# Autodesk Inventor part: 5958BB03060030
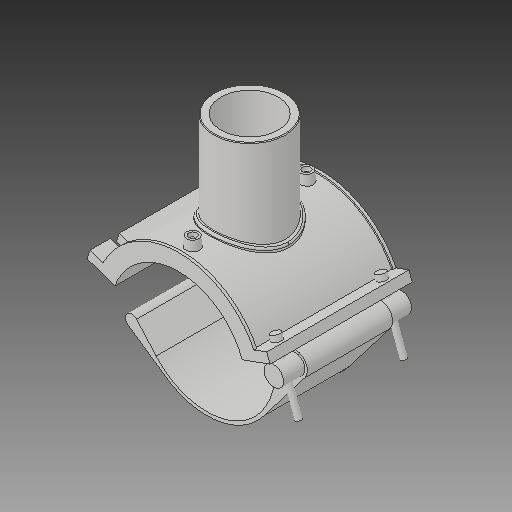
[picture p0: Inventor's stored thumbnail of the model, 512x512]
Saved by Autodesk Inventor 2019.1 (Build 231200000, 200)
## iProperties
Created: 2017-07
Part Number: 5958BB03060030
Material: Generic
Description: PLASSON BRANCH SADDLE 6'' x 3''
Document SubType Name: Modeling
Designer: KIM
Mass: 764.267 g
Surface Area: 1930.38 cm^2
Volume: 764.267 cm^3
Density: 1 g/cm^3
Appearance: Default
Author: KIM
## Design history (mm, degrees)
derived "5958B.ipt"
feature "Solid1::5958B.ipt"
feature "Solid2::5958B.ipt"
feature "Solid3::5958B.ipt"
tag "TaggingFeature1"
body "Solid1"
body "Solid2"
body "Solid3"
other parameters: "d_" = 168, "B_" = 173.736, "H_" = 106.934, "L_" = 176.022, "d_t" = 6, "d_1" = 88.7, "H_1" = 88.646, "d1" = 204.576, "d148" = 4.2, "d160" = 4.2, "d0" = 168, "d2" = 225.8568, "d3" = 42, "d4" = 176.022, "d5" = 0, "d6" = 0.1, "d8" = 0, "d19" = 6, "d20" = 6, "d21" = 105.6132, "d23" = 0, "d24" = 52.8066, "d26" = 0, "d27" = 3, "d28" = 3, "d29" = 3, "d30" = 56, "d31" = 6, "d32" = 0, "d33" = 0, "d34" = 0.6, "d40" = 106.37952, "d41" = 97.57, "d43" = 0, "d45" = 0, "d47" = 209.222, "d48" = 88.7, "d50" = 0, "d70" = 15, "d72" = 0, "d73" = 6, "d75" = 5, "d76" = 0, "d77" = 8.4, "d78" = 114, "d79" = 15, "d80" = 70.4088, "d82" = 5 deg, "d84" = 4, "d85" = 14, "d86" = 0, "d87" = 3, "d88" = 0, "d89" = 1, "d90" = 1, "d91" = 140.8176, "d92" = 0, "d93" = 0.5, "d94" = 88.42105, "d96" = 208.66752, "d97" = 3.52044, "d98" = 0, "d102" = 2.661, "d103" = 70.96, "d105" = 0, "d109" = -35.64467, "d117" = 0.887, "d120" = 140 deg, "d121" = 24.228, "d122" = 20 deg, "d123" = 409.152, "d124" = 122.7456, "d126" = 0, "d143" = 176.4, "d150" = 30.24, "d159" = 7.3152, "d161" = 4.2, "d162" = 105.6132, "d163" = 0, "d167" = 33.6, "d168" = 92.98909, "d173" = 1, "d175" = 84, "d176" = 20 deg, "d177" = 11.76, "d178" = 36.576, "d180" = 0, "d185" = 57.20715, "d186" = 57.20715, "d187" = 102.288, "d188" = 10.9728, "d189" = 11.76, "d190" = 0, "d191" = 153.432, "d200" = 18.288, "d202" = 0, "d216" = 158.4198, "d217" = 0, "d221" = 65.12814, "d222" = 11.76, "d223" = 7.056, "d224" = 84, "d225" = 7.056, "d227" = 24.192, "d230" = 109.2, "d236" = 11.5 deg, "d238" = 20 deg, "d239" = 11.76, "d240" = 0, "d241" = 0, "d242" = 6.2484
